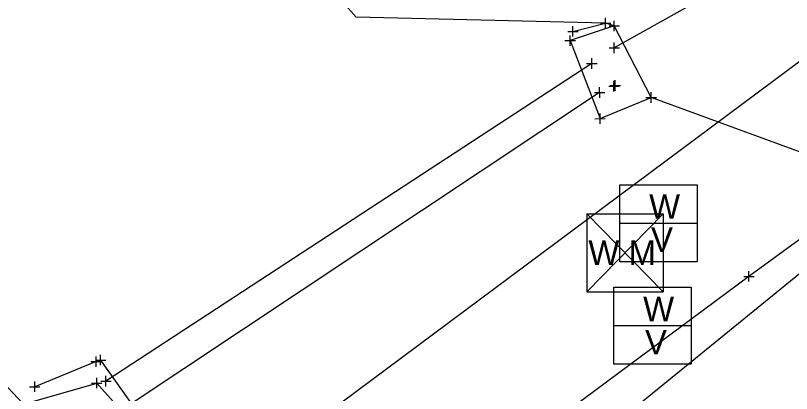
# Model space of a CAD drawing. Extents: x -1 to 1157254, y -1 to 2021979.
# Drawn here: x 1149882.2 to 1149976.9, y 2019409.5 to 2019455.6 of the extents above; entities that cross this region are included whole.
import ezdxf

# ---------------------------------------------------------------- set-up
doc = ezdxf.new("R2010")
doc.units = 0
for name, color, linetype in [('S_BUILDING_ANNOT', 7, 'Continuous'), ('S_CONTOUR_ANNOT', 7, 'Continuous'), ('S_CONTOUR_MINOR', 7, 'Continuous'), ('S_CTL_TABLE', 7, 'Continuous'), ('S_DITCHLINE', 7, 'Continuous'), ('S_DRIVEWAY_ANNOT', 7, 'Continuous'), ('S_DROP_INLET', 7, 'Continuous'), ('S_EDGE_BITUMINOUS', 7, 'Continuous'), ('S_EDGE_BITUMINOUS_ANNOT', 7, 'Continuous'), ('S_ELECTRIC_UTILITIES', 7, 'Continuous'), ('S_ELECTRIC_UTILITIES_ANNOT', 7, 'Continuous'), ('S_GAS_PUMP_ISLAND_ANNOT', 7, 'Continuous')]:
    doc.layers.add(name, color=color, linetype=linetype)

msp = doc.modelspace()

# ---------------------------------------------------------------- linework, layer by layer
at = {"layer": 'S_BUILDING_ANNOT'}
for p, q in [((1149954.639, 2019454.355), (1149955.911, 2019454.358)), ((1149955.276, 2019453.72), (1149955.274, 2019454.993)), ((1149955.275, 2019454.356), (1149955.275, 2019454.356)), ((1149949.255, 2019452.554), (1149950.527, 2019452.557)), ((1149949.892, 2019451.919), (1149949.889, 2019453.191)), ((1149949.891, 2019452.555), (1149949.891, 2019452.555)), ((1149955.267, 2019451.036), (1149955.265, 2019452.308)), ((1149955.267, 2019451.036), (1149955.265, 2019452.308)), ((1149954.63, 2019451.671), (1149955.902, 2019451.674)), ((1149954.63, 2019451.671), (1149955.902, 2019451.674)), ((1149955.266, 2019451.672), (1149955.266, 2019451.672)), ((1149955.266, 2019451.672), (1149955.266, 2019451.672)), ((1149951.894, 2019449.759), (1149953.166, 2019449.761)), ((1149951.894, 2019449.759), (1149953.166, 2019449.761)), ((1149952.531, 2019449.124), (1149952.529, 2019450.396)), ((1149952.531, 2019449.124), (1149952.529, 2019450.396)), ((1149952.53, 2019449.76), (1149952.53, 2019449.76)), ((1149952.53, 2019449.76), (1149952.53, 2019449.76)), ((1149955.225, 2019446.365), (1149955.223, 2019447.637)), ((1149955.394, 2019446.447), (1149955.392, 2019447.719)), ((1149953.489, 2019445.591), (1149953.487, 2019446.863)), ((1149953.489, 2019445.591), (1149953.487, 2019446.863)), ((1149954.588, 2019447), (1149955.86, 2019447.002)), ((1149954.757, 2019447.082), (1149956.029, 2019447.084)), ((1149955.224, 2019447.001), (1149955.224, 2019447.001)), ((1149955.393, 2019447.083), (1149955.393, 2019447.083)), ((1149952.852, 2019446.226), (1149954.124, 2019446.228)), ((1149952.852, 2019446.226), (1149954.124, 2019446.228)), ((1149953.488, 2019446.227), (1149953.488, 2019446.227)), ((1149953.488, 2019446.227), (1149953.488, 2019446.227)), ((1149959.776, 2019444.977), (1149959.773, 2019446.249)), ((1149959.138, 2019445.612), (1149960.41, 2019445.614)), ((1149959.774, 2019445.613), (1149959.774, 2019445.613)), ((1149952.895, 2019443.03), (1149954.167, 2019443.032)), ((1149953.532, 2019442.395), (1149953.53, 2019443.667)), ((1149953.531, 2019443.031), (1149953.531, 2019443.031)), ((1149971.69, 2019423.144), (1149971.687, 2019424.416)), ((1149971.052, 2019423.779), (1149972.325, 2019423.781)), ((1149971.689, 2019423.78), (1149971.689, 2019423.78)), ((1149891.984, 2019413.559), (1149893.257, 2019413.562)), ((1149892.07, 2019412.734), (1149892.067, 2019414.007)), ((1149892.622, 2019412.925), (1149892.619, 2019414.197)), ((1149892.621, 2019413.561), (1149892.621, 2019413.561)), ((1149891.432, 2019413.369), (1149892.705, 2019413.372)), ((1149892.069, 2019413.371), (1149892.069, 2019413.371)), ((1149893.277, 2019410.356), (1149893.274, 2019411.629)), ((1149884.599, 2019409.677), (1149884.596, 2019410.95)), ((1149891.52, 2019410.752), (1149892.793, 2019410.755)), ((1149892.158, 2019410.117), (1149892.155, 2019411.39)), ((1149892.157, 2019410.754), (1149892.157, 2019410.754)), ((1149892.639, 2019410.991), (1149893.912, 2019410.994)), ((1149893.276, 2019410.993), (1149893.276, 2019410.993)), ((1149883.961, 2019410.312), (1149885.234, 2019410.315)), ((1149884.597, 2019410.314), (1149884.597, 2019410.314))]:
    msp.add_line(p, q, dxfattribs=at)
at = {"layer": 'S_CONTOUR_ANNOT'}
for p, q in [((1149955.968, 2019434.968), (1149965.38, 2019434.968)), ((1149955.968, 2019425.556), (1149955.968, 2019434.968)), ((1149965.38, 2019434.968), (1149965.38, 2019425.556)), ((1149951.908, 2019431.4), (1149961.243, 2019431.4)), ((1149951.908, 2019431.4), (1149951.908, 2019421.91)), ((1149951.908, 2019431.4), (1149961.243, 2019421.91)), ((1149961.243, 2019431.4), (1149951.908, 2019421.91)), ((1149961.243, 2019431.4), (1149961.243, 2019421.91)), ((1149955.968, 2019430.281), (1149965.38, 2019430.281)), ((1149965.38, 2019425.556), (1149955.968, 2019425.556)), ((1149955.235, 2019422.465), (1149964.647, 2019422.465)), ((1149955.235, 2019413.052), (1149955.235, 2019422.465)), ((1149964.647, 2019422.465), (1149964.647, 2019413.052)), ((1149951.908, 2019421.91), (1149961.243, 2019421.91)), ((1149955.235, 2019417.778), (1149964.647, 2019417.778)), ((1149964.647, 2019413.052), (1149955.235, 2019413.052))]:
    msp.add_line(p, q, dxfattribs=at)
msp.add_lwpolyline([(1150776.076, 2020000.057), (1150711.77, 2019956.258), (1150627.272, 2019900.658), (1150578.771, 2019864.961), (1150479.116, 2019798.677), (1150423.47, 2019764.157), (1150358.501, 2019722.728), (1150313.965, 2019690.006), (1150273.946, 2019661.03), (1150225.644, 2019623.265), (1150033.499, 2019468.903), (1149971.689, 2019423.78), (1149931.587, 2019393.984), (1149688.417, 2019230.924)], dxfattribs=at)
at = {"layer": 'S_CONTOUR_MINOR'}
msp.add_lwpolyline([(1150216.083, 2019627.58), (1149895.482, 2019388.623)], dxfattribs=at)
at = {"layer": 'S_CTL_TABLE'}
for p, q in [((1149954.21, 2019454.051), (1149954.208, 2019455.324)), ((1149950.227, 2019453.053), (1149950.224, 2019454.326)), ((1149953.573, 2019454.686), (1149954.845, 2019454.689)), ((1149954.209, 2019454.687), (1149954.209, 2019454.687)), ((1149949.59, 2019453.688), (1149950.862, 2019453.691)), ((1149950.226, 2019453.689), (1149950.226, 2019453.689))]:
    msp.add_line(p, q, dxfattribs=at)
at = {"layer": 'S_DITCHLINE'}
for points in [[(1150096.227, 2019530.523), (1149955.266, 2019451.672)], [(1149952.53, 2019449.76), (1149893.276, 2019410.993)], [(1149953.488, 2019446.227), (1149895.509, 2019407.654)]]:
    msp.add_lwpolyline(points, dxfattribs=at)
at = {"layer": 'S_DRIVEWAY_ANNOT'}
msp.add_lwpolyline([(1149861.938, 2019435.657), (1149872.829, 2019419.202), (1149883.233, 2019408.163), (1149892.157, 2019410.754), (1149894.826, 2019407.771), (1149889.567, 2019400.65), (1149875.13, 2019388.23), (1149859.334, 2019370.679), (1149852.846, 2019375.884), (1149847.97, 2019397.873), (1149843.616, 2019425.468)], dxfattribs=at)
at = {"layer": 'S_DROP_INLET'}
msp.add_lwpolyline([(1150343.794, 2019722.309), (1149825.672, 2019300.101)], dxfattribs=at)
at = {"layer": 'S_EDGE_BITUMINOUS'}
msp.add_lwpolyline([(1149892.069, 2019413.371), (1149884.597, 2019410.314)], dxfattribs=at)
at = {"layer": 'S_EDGE_BITUMINOUS_ANNOT'}
msp.add_lwpolyline([(1149950.226, 2019453.689), (1149954.209, 2019454.687)], dxfattribs=at)
at = {"layer": 'S_ELECTRIC_UTILITIES'}
msp.add_lwpolyline([(1149949.891, 2019452.555), (1149953.531, 2019443.031), (1149959.774, 2019445.613), (1149955.275, 2019454.356)], close=True, dxfattribs=at)
at = {"layer": 'S_ELECTRIC_UTILITIES_ANNOT'}
msp.add_lwpolyline([(1149892.621, 2019413.561), (1149897.777, 2019406.278)], dxfattribs=at)
at = {"layer": 'S_GAS_PUMP_ISLAND_ANNOT'}
msp.add_lwpolyline([(1150005.492, 2019428.837), (1149959.774, 2019445.613), (1149955.275, 2019454.356), (1149954.209, 2019454.687), (1149923.801, 2019455.422), (1149782.11, 2019614.839)], dxfattribs=at)

# ---------------------------------------------------------------- texts
at = {"layer": 'S_CONTOUR_ANNOT'}
for s, height, p in [('W', 2.999, (1149959.517, 2019430.813)), ('V', 2.999, (1149959.753, 2019426.751)), ('W M', 2.9988, (1149952.112, 2019425.169)), ('W', 2.999, (1149958.784, 2019418.309)), ('V', 2.999, (1149959.02, 2019414.248))]:
    msp.add_text(s, height=height, dxfattribs=at).set_placement(p)

doc.saveas('drawing.dxf')
